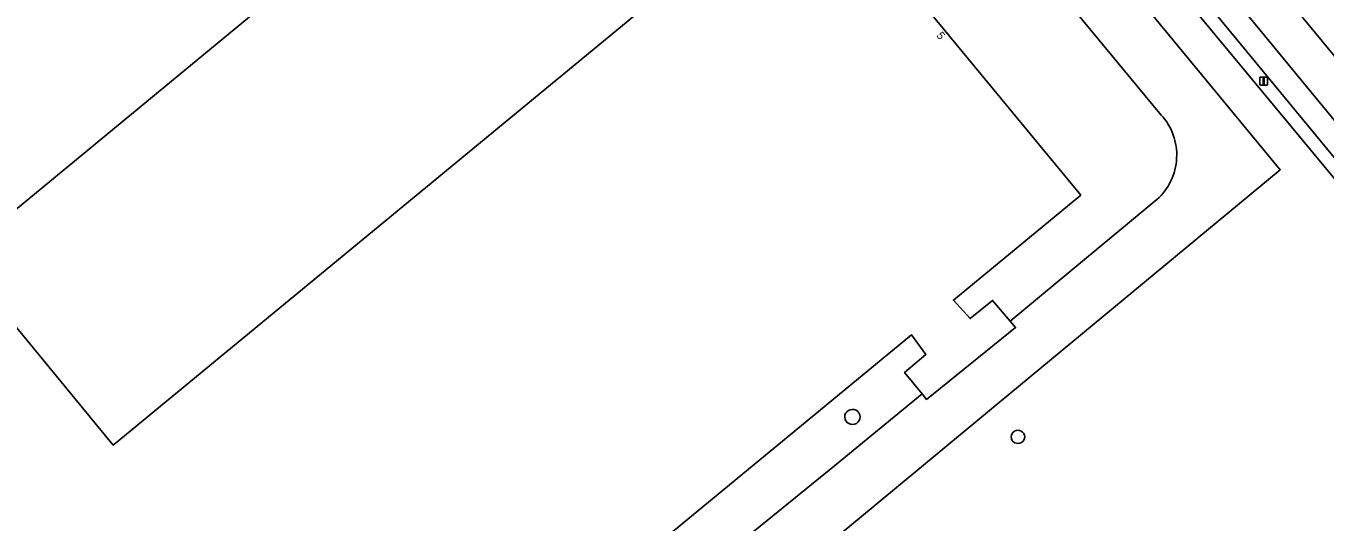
# Model space of a CAD drawing. Extents: x 156141 to 158132, y 385651 to 388333.
# Drawn here: x 157073.1 to 157235.4, y 386874.6 to 386936.6 of the extents above; entities that cross this region are included whole.
import ezdxf

# ---------------------------------------------------------------- set-up
doc = ezdxf.new("R2010")
doc.units = 0
for name, color, linetype in [('IMGEO_Berm_groen', 7, 'Continuous'), ('IMGEO_Erf', 7, 'Continuous'), ('IMGEO_Fietspad_gesloten', 7, 'Continuous'), ('IMGEO_Groenvoorziening', 7, 'Continuous'), ('IMGEO_Lichtmast', 7, 'Continuous'), ('IMGEO_Opslagtank', 7, 'Continuous'), ('IMGEO_Pand', 7, 'Continuous'), ('IMGEO_Pand_nummerreeks', 7, 'Continuous'), ('IMGEO_Rijbaan_lokaal_gesloten', 7, 'Continuous'), ('IMGEO_Rijbaan_lokaal_open', 7, 'Continuous')]:
    doc.layers.add(name, color=color, linetype=linetype)

msp = doc.modelspace()

# ---------------------------------------------------------------- linework, layer by layer
at = {"layer": 'IMGEO_Berm_groen'}
msp.add_lwpolyline([(157057.76, 387136.6), (157056.49, 387135.39), (157065.43, 387124.28), (157072.38, 387115.63), (157084.85, 387100.37), (157091.86, 387091.79), (157124.73, 387051.94), (157124.86, 387052.05), (157127.14, 387049.25), (157127.01, 387049.14), (157129.18, 387046.53), (157129.35, 387046.65), (157137.21, 387037.65), (157168.24, 387000), (157241.17, 386912.07), (157242.5, 386913.02), (157170.76, 387000), (157164.67, 387007.38)], dxfattribs=at)
msp.add_lwpolyline([(157195.98, 386982.1), (157193.26, 386979.85), (157193.01, 386977.75), (157252.99, 386904.94), (157255.08, 386904.74), (157257.99, 386906.97)], close=True, dxfattribs=at)
at = {"layer": 'IMGEO_Erf'}
for points in [[(157284.19, 386849.46), (157288.72, 386853.16), (157259.1, 386889.06), (157240.87, 386911.8), (157241.17, 386912.07), (157168.24, 387000), (157137.21, 387037.65), (157129.35, 387046.65), (157129.18, 387046.53), (157127.01, 387049.14), (157127.14, 387049.25), (157124.86, 387052.05), (157124.73, 387051.94), (157091.86, 387091.79), (157084.85, 387100.37), (157072.38, 387115.63), (157065.43, 387124.28), (157056.49, 387135.39), (157053.95, 387138.53), (157050.66, 387135.79), (157078.51, 387102.05), (157081.95, 387097.87), (157229.85, 386918.64), (157160.83, 386861.48)], [(157156.44, 386867.28), (157174.17, 386881.65), (157185.09, 386890.64), (157182.9, 386893.32), (157185.57, 386895.57), (157183.76, 386898.02), (157100.14, 386829.08), (157102.7, 386825.8), (157089.78, 386815.17), (157089.9, 386814.87)]]:
    msp.add_lwpolyline(points, dxfattribs=at)
for centre, radius, start, end in [((157176.37, 386887.76), 0.942, 89.9808, 273.1829), ((157176.41, 386887.76), 0.942, 270.6494, 92.5143), ((157197.05, 386885.27), 0.823, 89.6447, 272.7931), ((157197.09, 386885.27), 0.823, 270.0595, 92.3782)]:
    msp.add_arc(centre, radius, start, end, dxfattribs=at)
at = {"layer": 'IMGEO_Fietspad_gesloten'}
for points in [[(157255.95, 386901.35), (157252.99, 386904.94), (157193.01, 386977.75), (157190.16, 386981.21), (157174.68, 387000), (157166.89, 387009.45)], [(157164.67, 387007.38), (157170.76, 387000), (157242.5, 386913.02), (157260.15, 386891.62), (157276.21, 386872.22), (157291.72, 386853.57), (157295.69, 386848.8), (157300.18, 386843.65), (157300.3, 386843.52), (157300.52, 386843.27), (157300.61, 386843.16), (157300.77, 386842.97), (157305.03, 386838.05), (157305.21, 386837.84), (157306.25, 386836.69), (157307.17, 386835.58), (157317.74, 386823.13), (157324.43, 386815.04), (157329.8, 386808.57), (157345.28, 386789.91), (157378.22, 386750), (157413.31, 386707.49), (157450.57, 386662.3)]]:
    msp.add_lwpolyline(points, dxfattribs=at)
at = {"layer": 'IMGEO_Groenvoorziening'}
for points in [[(157214.97, 386925.48), (157169.44, 386980.52), (157143.68, 387011.99), (157121.58, 387038.54), (157110.85, 387029.54), (157151.92, 386979.73), (157064.67, 386907.78), (157084.05, 386884.24), (157171.32, 386956.18)], [(157171.32, 386956.18), (157204.92, 386915.47), (157189.01, 386902.35), (157191.11, 386900.04), (157193.9, 386902.32), (157196.1, 386899.73), (157214.42, 386914.91)]]:
    msp.add_lwpolyline(points, dxfattribs=at)
msp.add_arc((157209.47, 386920.47), 7.44, 311.7538, 42.3613, dxfattribs=at)
at = {"layer": 'IMGEO_Lichtmast'}
for p, q in [((157227.27, 386929.33), (157227.27, 386930.13)), ((157227.27, 386930.13), (157227.27, 386929.33)), ((157227.37, 386930.23), (157228.16, 386930.23)), ((157228.16, 386930.23), (157227.37, 386930.23)), ((157228.16, 386929.23), (157227.37, 386929.23)), ((157227.37, 386929.23), (157228.16, 386929.23)), ((157228.26, 386930.13), (157228.26, 386929.33)), ((157228.26, 386929.33), (157228.26, 386930.13))]:
    msp.add_line(p, q, dxfattribs=at)
msp.add_lwpolyline([(157227.69, 386930.1), (157227.84, 386930.1), (157227.84, 386929.35), (157227.69, 386929.35), (157227.69, 386930.1)], dxfattribs=at)
for centre, start, end in [((157227.37, 386930.13), 90, 180), ((157227.37, 386930.13), 90, 180), ((157227.37, 386929.33), 180, 270), ((157227.37, 386929.33), 180, 270), ((157228.16, 386930.13), 0, 90), ((157228.16, 386930.13), 360, 90), ((157228.16, 386929.33), 270, 0), ((157228.16, 386929.33), 270, 0)]:
    msp.add_arc(centre, 0.1, start, end, dxfattribs=at)
at = {"layer": 'IMGEO_Opslagtank'}
for centre, radius, start, end in [((157176.37, 386887.76), 0.942, 89.9808, 273.1829), ((157176.41, 386887.76), 0.942, 270.6494, 92.5143), ((157197.05, 386885.27), 0.823, 89.6447, 272.7931), ((157197.09, 386885.27), 0.823, 270.0595, 92.3782)]:
    msp.add_arc(centre, radius, start, end, dxfattribs=at)
at = {"layer": 'IMGEO_Pand'}
msp.add_lwpolyline([(157100.14, 386829.08), (157183.76, 386898.02), (157185.57, 386895.57), (157182.9, 386893.32), (157185.09, 386890.64), (157185.65, 386889.95), (157196.78, 386898.93), (157196.1, 386899.73), (157193.9, 386902.32), (157191.11, 386900.04), (157189.01, 386902.35), (157204.92, 386915.47), (157171.32, 386956.18), (157084.05, 386884.24), (157064.67, 386907.78), (157151.92, 386979.73), (157110.85, 387029.54), (157092.5, 387051.8)], dxfattribs=at)
at = {"layer": 'IMGEO_Rijbaan_lokaal_gesloten'}
msp.add_lwpolyline([(157117.1, 387077.69), (157144.85, 387044.06), (157151.82, 387035.62), (157159.75, 387026), (157181.21, 387000), (157194.91, 386983.4), (157195.98, 386982.1), (157257.99, 386906.97)], dxfattribs=at)
at = {"layer": 'IMGEO_Rijbaan_lokaal_open'}
for points in [[(157160.83, 386861.48), (157229.85, 386918.64), (157081.95, 387097.87), (157078.51, 387102.05), (157072.84, 387097.37), (157076.28, 387093.24), (157099.26, 387065.6)], [(157098.79, 387057.2), (157092.5, 387051.8), (157110.85, 387029.54), (157121.58, 387038.54), (157143.68, 387011.99), (157169.44, 386980.52), (157214.97, 386925.48)], [(157214.42, 386914.91), (157196.1, 386899.73), (157196.78, 386898.93), (157185.65, 386889.95), (157185.09, 386890.64), (157174.17, 386881.65), (157156.44, 386867.28), (157104.12, 386824), (157094.13, 386815.73)]]:
    msp.add_lwpolyline(points, dxfattribs=at)
msp.add_arc((157209.47, 386920.47), 7.44, 311.7538, 42.3613, dxfattribs=at)

# ---------------------------------------------------------------- texts
at = {"layer": 'IMGEO_Pand_nummerreeks'}
msp.add_text('5', height=1, rotation=309.5281, dxfattribs=at).set_placement((157186.83, 386935.38))

doc.saveas('drawing.dxf')
